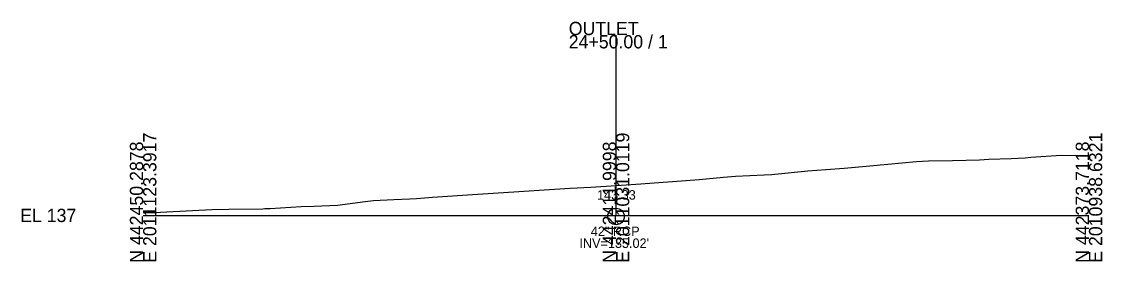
# Model space of a CAD drawing. Extents: x -26 to 1203, y -15 to 9526.
# Drawn here: x 974.3 to 1202.8, y 4490.3 to 4540.9 of the extents above; entities that cross this region are included whole.
import ezdxf

# ---------------------------------------------------------------- set-up
doc = ezdxf.new("R2010")
doc.units = 0
for name, color, linetype in [('Exist Cross Section Cell', 7, 'Continuous'), ('Exist XS Center Line Elevation Label', 7, 'Continuous'), ('Exist XS Ground Line', 7, 'Continuous'), ('Prop XSC Text', 7, 'Continuous')]:
    doc.layers.add(name, color=color, linetype=linetype)

msp = doc.modelspace()

# ---------------------------------------------------------------- linework, layer by layer
at = {"layer": 'Exist Cross Section Cell'}
for p, q in [((1100, 4500), (1100, 4538.06)), ((1000, 4500), (1100, 4500)), ((1100, 4500), (1200, 4500))]:
    msp.add_line(p, q, dxfattribs=at)
at = {"layer": 'Exist XS Ground Line'}
msp.add_lwpolyline([(1000, 4500.63), (1000.75, 4500.63), (1002.82, 4500.6), (1003.67, 4500.67), (1010.47, 4501.07), (1014.5, 4501.22), (1018.12, 4501.29), (1025.32, 4501.4), (1025.77, 4501.43), (1026.87, 4501.49), (1033.43, 4501.85), (1036.15, 4501.95), (1041.08, 4502.16), (1046.97, 4502.96), (1048.73, 4503.13), (1052.99, 4503.36), (1056.39, 4503.49), (1057.8, 4503.55), (1061.2, 4503.89), (1068.62, 4504.37), (1079.45, 4505.04), (1087, 4505.54), (1090.27, 4505.76), (1094.65, 4505.99), (1100, 4506.33), (1101.1, 4506.4), (1105.22, 4506.69), (1109.96, 4507.05), (1111.92, 4507.15), (1117.61, 4507.55), (1122.75, 4508.09), (1125.26, 4508.29), (1131.34, 4508.57), (1132.92, 4508.65), (1133.57, 4508.69), (1140.57, 4509.39), (1144.39, 4509.67), (1148.22, 4509.97), (1155.22, 4510.62), (1155.88, 4510.67), (1157.46, 4510.82), (1163.53, 4511.36), (1166.04, 4511.55), (1171.18, 4511.61), (1176.87, 4511.76), (1178.83, 4511.9), (1183.58, 4512.05), (1186.49, 4512.18), (1187.69, 4512.31), (1194.14, 4512.69), (1198.52, 4512.68), (1200, 4512.67)], dxfattribs=at)
at = {"layer": 'Prop XSC Text'}
msp.add_circle((1100, 4499.77), 1.75, dxfattribs=at)

# ---------------------------------------------------------------- texts
at = {"layer": 'Exist Cross Section Cell'}
for s, p in [('OUTLET', (1090, 4538.06)), ('24+50.00 / 1', (1090, 4535.26)), ('EL 137', (974, 4498.6))]:
    msp.add_text(s, height=2.8, dxfattribs=at).set_placement(p)
for s, p in [('E 2011123.3917', (1002.8, 4490)), ('E 2011031.0119', (1102.8, 4490)), ('E 2010938.6321', (1202.8, 4490)), ('N 442450.2878', (1000, 4490)), ('N 442411.9998', (1100, 4490)), ('N 442373.7118', (1200, 4490))]:
    msp.add_text(s, height=2.8, rotation=90, dxfattribs=at).set_placement(p)
at = {"layer": 'Exist XS Center Line Elevation Label'}
msp.add_text('143.33', height=2, dxfattribs=at).set_placement((1095.99, 4503.33))
at = {"layer": 'Prop XSC Text'}
for s, p in [('42" RCP', (1094.67, 4495.65)), ("INV=135.02'", (1092.26, 4493.14))]:
    msp.add_text(s, height=2, dxfattribs=at).set_placement(p)

doc.saveas('drawing.dxf')
